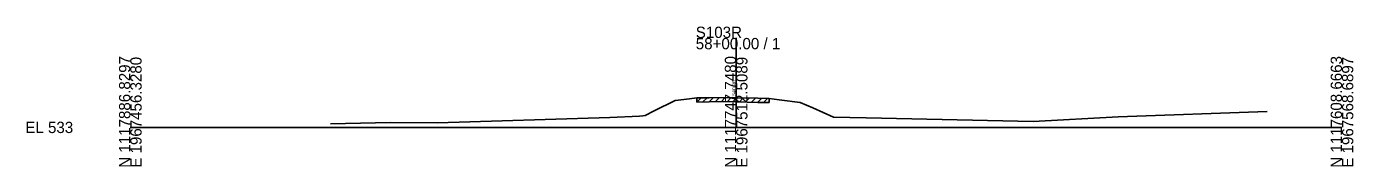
# Model space of a CAD drawing. Extents: x 974 to 1303, y 990 to 10019.
# Drawn here: x 974.3 to 1302.8, y 990.3 to 1025 of the extents above; entities that cross this region are included whole.
import ezdxf

# ---------------------------------------------------------------- set-up
doc = ezdxf.new("R2010")
doc.units = 0
for name, color, linetype in [('Level 10', 7, 'Continuous'), ('Level 60', 7, 'Continuous'), ('Level 61', 7, 'Continuous'), ('Level 63', 7, 'Continuous')]:
    doc.layers.add(name, color=color, linetype=linetype)

msp = doc.modelspace()

# ---------------------------------------------------------------- linework, layer by layer
at = {"layer": 'Level 60'}
for p, q in [((1129.7, 1004.08), (1134.9, 1006.66)), ((1134.9, 1006.66), (1138.44, 1007.08)), ((1138.44, 1007.08), (1140.29, 1007.29)), ((1140.29, 1007.29), (1143.36, 1007.32)), ((1143.36, 1007.32), (1149.1, 1007.39)), ((1149.1, 1007.39), (1150, 1007.36)), ((1150, 1007.36), (1155.33, 1007.21)), ((1155.33, 1007.21), (1158.17, 1007.13)), ((1158.17, 1007.13), (1160.65, 1006.83)), ((1160.65, 1006.83), (1165.84, 1006.18)), ((1165.84, 1006.18), (1168.98, 1004.87)), ((1076.09, 1001.15), (1118.74, 1002.45)), ((1118.74, 1002.45), (1126.1, 1002.75)), ((1126.1, 1002.75), (1126.89, 1002.87)), ((1126.89, 1002.87), (1127.44, 1002.94)), ((1127.44, 1002.94), (1129.7, 1004.08)), ((1168.98, 1004.87), (1174.07, 1002.54)), ((1174.07, 1002.54), (1182.16, 1002.41)), ((1182.16, 1002.41), (1223.5, 1001.5)), ((1223.5, 1001.5), (1244.59, 1002.61)), ((1244.59, 1002.61), (1281.48, 1003.97)), ((1049.53, 1000.92), (1064.46, 1001.22)), ((1064.46, 1001.22), (1076.09, 1001.15))]:
    msp.add_line(p, q, dxfattribs=at)
at = {"layer": 'Level 61'}
for p, q in [((1140.29, 1006.29), (1141.3, 1007.3)), ((1140.29, 1006.29), (1140.29, 1007.29)), ((1140.29, 1006.29), (1143.36, 1006.32)), ((1140.29, 1006.29), (1140.29, 1006.29)), ((1141.79, 1006.3), (1142.8, 1007.31)), ((1143.29, 1006.32), (1144.3, 1007.33)), ((1143.36, 1006.32), (1149.1, 1006.39)), ((1144.79, 1006.34), (1145.8, 1007.35)), ((1146.29, 1006.36), (1147.3, 1007.37)), ((1147.79, 1006.37), (1148.8, 1007.39)), ((1149.1, 1006.39), (1150, 1006.36)), ((1149.29, 1006.38), (1150.26, 1007.36)), ((1150, 1006.36), (1155.33, 1006.21)), ((1150.79, 1006.34), (1151.76, 1007.31)), ((1152.29, 1006.3), (1153.26, 1007.27)), ((1153.79, 1006.26), (1154.76, 1007.23)), ((1155.29, 1006.21), (1156.26, 1007.19)), ((1155.33, 1006.21), (1158.17, 1006.13)), ((1156.79, 1006.17), (1157.76, 1007.14)), ((1158.17, 1007.13), (1158.17, 1006.13))]:
    msp.add_line(p, q, dxfattribs=at)
at = {"layer": 'Level 63'}
for p, q in [((1150, 1000), (1150, 1022.17)), ((1000, 1000), (1150, 1000)), ((1150, 1000), (1300, 1000))]:
    msp.add_line(p, q, dxfattribs=at)

# ---------------------------------------------------------------- texts
at = {"layer": 'Level 10'}
msp.add_text('540.36', height=0.9, rotation=90, dxfattribs=at).set_placement((1149.95, 1007.86))
at = {"layer": 'Level 63'}
for s, p in [('58+00.00 / 1', (1140, 1019.37)), ('S103R', (1140, 1022.17)), ('EL 533', (974, 998.6))]:
    msp.add_text(s, height=2.8, dxfattribs=at).set_placement(p)
for s, p in [('N 1117886.8297', (1000, 990)), ('E 1967456.3280', (1002.8, 990)), ('N 1117747.7480', (1150, 990)), ('E 1967512.5089', (1152.8, 990)), ('N 1117608.6663', (1300, 990)), ('E 1967568.6897', (1302.8, 990))]:
    msp.add_text(s, height=2.8, rotation=90, dxfattribs=at).set_placement(p)

doc.saveas('drawing.dxf')
